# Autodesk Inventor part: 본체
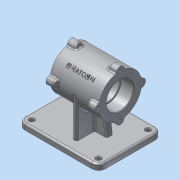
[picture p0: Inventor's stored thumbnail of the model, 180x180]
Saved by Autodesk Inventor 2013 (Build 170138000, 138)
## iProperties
Created: 2015-12
Part Number: 본체
Material: 알루미늄 6061
Document SubType Name: Modeling
Designer: dgall
Density: 2.71 g/cm^3
Mass: 1163.86 g
Surface Area: 818.799 cm^2
Volume: 429.47 cm^3
Author: dgall
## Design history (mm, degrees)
sketch "스케치1"
  geometry: C1 r 37 at (0, 0); 1 further point
  constraints: 1 centre point, 1 coincident
  dimensions: "d0" = 74 diameter of C1
extrude "돌출1" new body sketch "스케치1" stored distance "d1" = 85; taper "d2" = 0 deg
sketch "스케치2"
  geometry: L1 (0, 42.5)-(0, -42.5); L2 (0, 42.5)-(23.5, 42.5); L3 (23.5, 42.5)-(23.5, 20.5); L4 (23.5, 20.5)-(21, 20.5); L5 (21, 20.5)-(21, -20.5); L6 (21, -20.5)-(23.5, -20.5); L7 (23.5, -20.5)-(23.5, -42.5); L8 (23.5, -42.5)-(0, -42.5); 2 further points
  constraints: 16 end point, 4 parallel, 2 perpendicular, 1 coincident, 1 collinear, 1 midpoint, 1 vertical
  dimensions: "d3" = 85 distance of L1.start L1.end; "d5" = 47 diameter of L3 L1; "d6" = 47 diameter of L7 L1; "d7" = 42 diameter of L5 L1; "d8" = 22 distance of L2.end L3.end; "d9" = 22 distance of L6.end L7.end
revolve "회전1" sketch "스케치2" stored, may be unused: angle "d10" = 90 deg
sketch "스케치3"
  geometry: C1 r 23.5 at (0, 0) reference; C2 r 7 at (0, 37); 1 further point
  constraints: 2 vertical alignment, 1 centre point, 1 other
  dimensions: "d11" = 14 diameter of C2
node "작업 평면1"
sketch "스케치4"
  geometry: L1 (55, 80)-(-55, 80); L2 (-55, 80)-(-55, -60); L3 (-55, -60)-(55, -60); L4 (55, -60)-(55, 80); L5 (37, 4)-(-37, 4); L6 (-37, 4)-(-37, -4); L7 (-37, -4)-(37, -4); L8 (37, -4)-(37, 4); 5 further points
  constraints: 16 end point, 4 midpoint, 4 parallel, 2 horizontal, 2 perpendicular, 2 vertical alignment, 1 horizontal alignment
  dimensions: "d13" = 140 distance of L3.end L1.start; "d15" = 110 distance of L2.end L3.end; "d16" = 8 distance of L7.end L5.start; "d17" = 76 distance between parallel lines of L1 L5; "d18" = 74 distance of L6.end L7.end
extrude "돌출2" join sketch "스케치4" distance "d19" = 10; taper "d20" = 0 deg
extrude "돌출3" join sketch "스케치4" stored distance "d21" = 10; taper "d22" = 0 deg
sketch "스케치5"
  geometry: L1 (-70, -60)-(-70, 80) reference; L2 (-37, 20.948)-(-70, 25); L3 (-37, -20.948)-(-70, -25); L4 (37, 42.5)-(-37, 42.5) reference; 2 further points
  constraints: 4 end point, 2 point on line
  dimensions: "d24" = 50 distance of L3.end L2.end; "d25" = 21 distance of point (-70, 4) L2.end; "d26" = 97 deg angle of L1 L2; "d27" = 97 deg angle of L1 L3
feature "리브1" sketch "스케치5" dims "d28" = 1, "d29" = 12, "d30" = 0, "d31" = 0, "d32" = 1, "d33" = 1
node "작업 평면3"
extrude "돌출4" join sketch "스케치3" distance "d34" = 12.452; taper "d35" = 0 deg
sketch "스케치7"
  geometry: L1 (44, 42.5)-(44, 30.048) reference; L2 (37, -42.5)-(37, 30.048) reference; L3 (44, 30.048)-(34, 26.408); L4 (34, 30.5)-(44, 30.5); L5 (34, 30.5)-(34, 26.408); 2 further points
  constraints: 6 end point, 3 point on line, 2 perpendicular
  dimensions: "d41" = 110 deg angle of L2 L3; "d76" = 4.09191 distance of L4.start L3.end; "d78" = 10 distance of L4.start L4.end
extrude "돌출5" join sketch "스케치7" stored distance "d44" = 14; taper "d45" = 0 deg
sketch "스케치8"
  geometry: L1 (-9, 45)-(9, 45); L2 (9, 45)-(9, 35.889); L3 (-9, 35.889)-(-9, 45); C1 r 23.5 at (0, 0) reference; A1 r 7 centre (0, 37) between (6.969, 36.338) and (-6.969, 36.338) reference; A2 r 7 centre (0, 37) between (6.969, 36.338) and (-6.969, 36.338); A3 r 37 centre (0, 0) between (9, 35.889) and (6.969, 36.338); A4 r 37 centre (0, 0) between (-6.969, 36.338) and (-9, 35.889); 1 further point
  constraints: 6 end point, 6 point on circle, 3 centre point, 2 coincident, 1 horizontal, 1 parallel, 1 perpendicular, 1 vertical alignment
  dimensions: "d50" = 14 diameter of A2; "d51" = 18 distance of L1.start L1.end; "d54" = 9.11128 distance of L3.start L1.start; "d55" = 9.11128 distance of L1.end L2.end; "d57" = 37 radius of A4; "d58" = 37 radius of A3
extrude "돌출6" cut sketch "스케치8" distance "d59" = 20; taper "d60" = 0 deg
node "작업 평면4"
hole "구멍1" diameter "d66" = 3.459; stored, may be unused: countersink angle "d70" = 90 deg, drill point angle "d72" = 118 deg; dims "d64" = 10, "d65" = 10, "d67" = 9, "d68" = 4, "d69" = 2, "d71" = 11
fillet "모깎기1" dims "d79" = 12
hole "구멍2" diameter "d82" = 8; stored, may be unused: countersink angle "d86" = 90 deg, drill point angle "d88" = 0 deg; dims "d80" = 10, "d81" = 10, "d83" = 9, "d84" = 4, "d85" = 2, "d87" = 11
fillet "모깎기11" dims "d110" = 3
fillet "모깎기12" dims "d111" = 3
chamfer "모따기1" distance "d95" = 1; stored, may be unused: second distance "d96" = 2, angle "d97" = 45 deg
chamfer "모따기2" distance "d98" = 1; stored, may be unused: second distance "d99" = 2, angle "d100" = 45 deg
fillet "모깎기2" dims "d101" = 0.3
fillet "모깎기5" dims "d104" = 3
node "작업 평면6"
  node "작업 평면5"
sketch "스케치9"
  geometry: 2 further points
  constraints: 1 coincident, 1 other
feature "엠보싱1" sketch "스케치9" dims "d0" = 74, "d11" = 14, "d114" = 0.5, "d115" = 0
fillet "모깎기17" dims "d120" = 3
fillet "모깎기18" dims "d121" = 3
fillet "모깎기19" dims "d122" = 3
node "솔리드1"
mirror "대칭1"
pattern_circular "원형 패턴1" dims "d62" = 360 deg
mirror "대칭2"
pattern_circular "원형 패턴2" dims angle "d74" = 360 deg
mirror "대칭3"
pattern_linear "직사각형 패턴1" dims "d91" = 116, "d94" = 86
other parameters: "d49" = 2, "d56" = 74, "d112" = -45 deg, "d113" = 45
